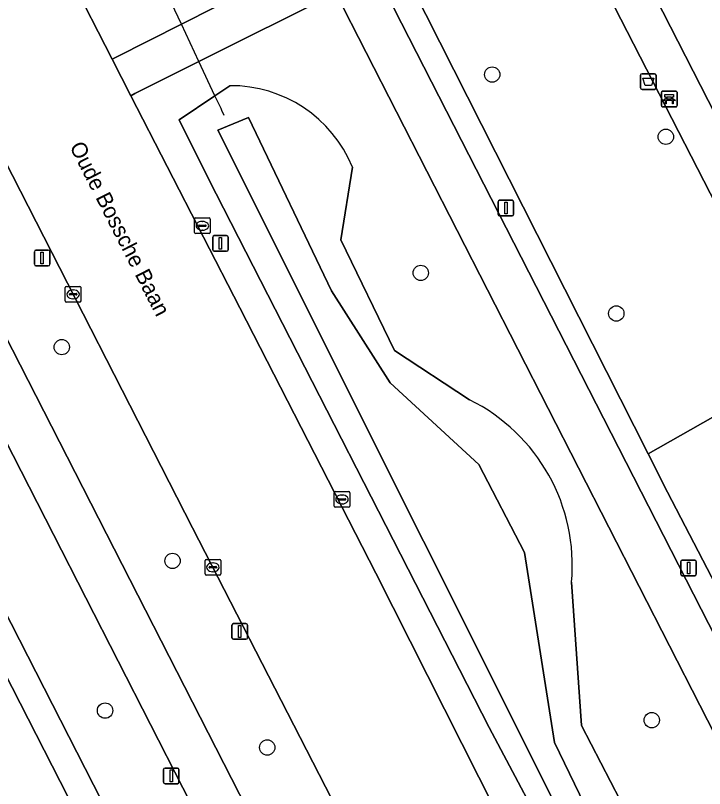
# Model space of a CAD drawing. Extents: x 159352 to 160617, y 385888 to 387323.
# Drawn here: x 159737.07 to 159781, y 386580.69 to 386630 of the extents above; entities that cross this region are included whole.
import ezdxf

# ---------------------------------------------------------------- set-up
doc = ezdxf.new("R2010")
doc.units = 0
for name, color, linetype in [('IMGEO_Afvalbak', 7, 'Continuous'), ('IMGEO_Bank', 7, 'Continuous'), ('IMGEO_Berm_groen', 7, 'Continuous'), ('IMGEO_Boom', 7, 'Continuous'), ('IMGEO_Duiker', 7, 'Continuous'), ('IMGEO_Fietspad_gesloten', 7, 'Continuous'), ('IMGEO_Groenvoorziening', 7, 'Continuous'), ('IMGEO_Kolk', 7, 'Continuous'), ('IMGEO_Lichtmast', 7, 'Continuous'), ('IMGEO_Oever', 7, 'Continuous'), ('IMGEO_Openbare_ruimte_label', 7, 'Continuous'), ('IMGEO_Rijbaan_lokaal_gesloten', 7, 'Continuous'), ('IMGEO_Verkeersbordpaal', 7, 'Continuous'), ('IMGEO_Voetpad_halfverhard', 7, 'Continuous'), ('IMGEO_Voetpad_open', 7, 'Continuous'), ('IMGEO_Waterloop', 7, 'Continuous')]:
    doc.layers.add(name, color=color, linetype=linetype)

msp = doc.modelspace()

# ---------------------------------------------------------------- linework, layer by layer
at = {"layer": 'IMGEO_Afvalbak'}
for p, q in [((159776.915, 386625.381), (159776.915, 386626.181)), ((159776.915, 386626.181), (159776.915, 386625.381)), ((159777.015, 386626.281), (159777.805, 386626.281)), ((159777.805, 386626.281), (159777.015, 386626.281)), ((159777.905, 386626.181), (159777.905, 386625.381)), ((159777.905, 386625.381), (159777.905, 386626.181)), ((159777.805, 386625.281), (159777.015, 386625.281)), ((159777.015, 386625.281), (159777.805, 386625.281))]:
    msp.add_line(p, q, dxfattribs=at)
msp.add_lwpolyline([(159777.058, 386625.995), (159777.762, 386625.995), (159777.613, 386625.525), (159777.207, 386625.525), (159777.058, 386625.995)], dxfattribs=at)
for centre, start, end in [((159777.015, 386626.181), 90, 180), ((159777.015, 386626.181), 90, 180), ((159777.805, 386626.181), 0, 90), ((159777.805, 386626.181), 360, 90), ((159777.015, 386625.381), 180, 270), ((159777.015, 386625.381), 180, 270), ((159777.805, 386625.381), 270, 0), ((159777.805, 386625.381), 270, 0)]:
    msp.add_arc(centre, 0.1, start, end, dxfattribs=at)
at = {"layer": 'IMGEO_Bank'}
for p, q in [((159778.244, 386624.243), (159778.244, 386625.084)), ((159778.244, 386625.084), (159778.244, 386624.243)), ((159778.319, 386625.168), (159779.16, 386625.168)), ((159779.16, 386625.168), (159778.319, 386625.168)), ((159779.244, 386625.093), (159779.244, 386624.252)), ((159779.244, 386624.252), (159779.244, 386625.093)), ((159778.941, 386624.566), (159778.548, 386624.566)), ((159778.553, 386624.674), (159778.553, 386624.78)), ((159778.597, 386624.78), (159778.597, 386624.674)), ((159778.885, 386624.786), (159778.603, 386624.786)), ((159778.603, 386624.668), (159778.885, 386624.668)), ((159778.891, 386624.674), (159778.891, 386624.78)), ((159778.935, 386624.78), (159778.935, 386624.674)), ((159779.169, 386624.168), (159778.328, 386624.168)), ((159778.328, 386624.168), (159779.169, 386624.168))]:
    msp.add_line(p, q, dxfattribs=at)
for points in [[(159778.491, 386624.566), (159778.349, 386624.566), (159778.461, 386624.668), (159778.547, 386624.668)], [(159778.547, 386624.786), (159778.461, 386624.786), (159778.461, 386624.947), (159779.024, 386624.947), (159779.024, 386624.786), (159778.941, 386624.786)], [(159778.541, 386624.559), (159778.541, 386624.352), (159778.498, 386624.352), (159778.498, 386624.559)], [(159778.941, 386624.668), (159779.024, 386624.668), (159779.136, 386624.566), (159778.997, 386624.566)], [(159778.991, 386624.559), (159778.991, 386624.352), (159778.947, 386624.352), (159778.947, 386624.559)]]:
    msp.add_lwpolyline(points, dxfattribs=at)
for centre, radius, start, end in [((159778.322, 386625.09), 0.0779, 92.4484, 184.2845), ((159778.322, 386625.09), 0.0779, 92.4484, 184.2845), ((159779.166, 386625.09), 0.0779, 2.4484, 94.2845), ((159779.166, 386625.09), 0.0779, 2.4484, 94.2845), ((159778.491, 386624.559), 0.00671, 2.8957, 87.1043), ((159778.548, 386624.559), 0.00671, 92.8957, 177.1043), ((159778.546, 386624.779), 0.00671, 2.8957, 87.1043), ((159778.546, 386624.675), 0.00671, 272.8957, 357.1043), ((159778.603, 386624.779), 0.00671, 92.8957, 177.1043), ((159778.603, 386624.675), 0.00671, 182.8957, 267.1043), ((159778.885, 386624.779), 0.00671, 2.8957, 87.1043), ((159778.885, 386624.675), 0.00671, 272.8957, 357.1043), ((159778.942, 386624.779), 0.00671, 92.8957, 177.1043), ((159778.942, 386624.675), 0.00671, 182.8957, 267.1043), ((159778.94, 386624.559), 0.00671, 2.8957, 87.1043), ((159778.997, 386624.559), 0.00671, 92.8957, 177.1043), ((159778.322, 386624.246), 0.0779, 182.4484, 274.2845), ((159778.322, 386624.246), 0.0779, 182.4484, 274.2845), ((159779.166, 386624.246), 0.0779, 272.4484, 4.2845), ((159779.166, 386624.246), 0.0779, 272.4484, 4.2845)]:
    msp.add_arc(centre, radius, start, end, dxfattribs=at)
at = {"layer": 'IMGEO_Berm_groen'}
for points in [[(159672.985, 386771.072), (159673.306, 386770.324), (159675.396, 386765.976), (159673.079, 386764.76), (159673.972, 386762.988), (159680.607, 386750), (159680.941, 386749.346), (159691.569, 386728.727), (159695.538, 386720.97), (159702.544, 386706.95), (159713.2, 386686.195), (159726.157, 386660.692), (159735.251, 386642.791), (159743.239, 386627.211), (159743.502, 386627.346), (159747.647, 386629.447), (159756.288, 386633.826), (159699.609, 386744.934), (159693.118, 386741.84), (159693.16, 386741.671), (159703.621, 386721.304), (159711.807, 386715.609)], [(159772.521, 386593.855), (159773.159, 386584.718), (159780.543, 386570.427), (159778.249, 386569.078), (159776.147, 386567.841), (159767.261, 386584.583), (159749.402, 386619.536), (159747.519, 386623.348), (159749.791, 386624.879), (159750.739, 386625.518)], [(159758.553, 386620.328), (159757.812, 386615.682), (159761.24, 386608.621), (159766.017, 386605.488)]]:
    msp.add_lwpolyline(points, dxfattribs=at)
for points in [[(159757.502, 386631.446), (159748.768, 386627.059), (159744.692, 386625.012), (159744.434, 386624.88), (159751.377, 386611.341), (159760.048, 386594.429), (159767.715, 386579.24), (159775.346, 386564.177), (159775.69, 386564.351), (159779.629, 386566.369), (159788.426, 386570.875)], [(159748.365, 386597.323), (159736.391, 386620.747), (159731.872, 386618.458), (159762.831, 386557.859), (159767.368, 386560.207), (159764.513, 386565.852)], [(159729.174, 386617.087), (159724.727, 386614.834), (159755.671, 386554.225), (159760.103, 386556.503)]]:
    msp.add_lwpolyline(points, close=True, dxfattribs=at)
for centre, radius, start, end in [((159750.804, 386617.138), 8.38, 22.3723, 90.4441), ((159760.765, 386594.917), 11.804, 354.8391, 63.58)]:
    msp.add_arc(centre, radius, start, end, dxfattribs=at)
at = {"layer": 'IMGEO_Boom'}
for centre in [(159767.462, 386626.226), (159778.529, 386622.256), (159762.909, 386613.579), (159775.373, 386610.988), (159740.026, 386608.843), (159747.085, 386595.211), (159742.784, 386585.664), (159777.632, 386585.055), (159753.122, 386583.311)]:
    msp.add_circle(centre, 0.489, dxfattribs=at)
at = {"layer": 'IMGEO_Duiker'}
msp.add_lwpolyline([(159750.382, 386623.621), (159750.234, 386623.935), (159750.18, 386624.052), (159749.791, 386624.879), (159748.768, 386627.059), (159747.647, 386629.447), (159746.597, 386631.685), (159746.295, 386632.327), (159746.229, 386632.469), (159746.117, 386632.707)], dxfattribs=at)
at = {"layer": 'IMGEO_Fietspad_gesloten'}
for points in [[(159676.451, 386789.766), (159676.823, 386789.968), (159680.292, 386783.231), (159681.255, 386781.361), (159681.072, 386781.273), (159687.819, 386768.047), (159699.609, 386744.934), (159756.288, 386633.826), (159757.502, 386631.446), (159788.426, 386570.875), (159789.556, 386568.692), (159791.68, 386564.586)], [(159848.46, 386459.683), (159802.183, 386550.232), (159802.147, 386550.232), (159796.524, 386561.299), (159796.533, 386561.328), (159758.813, 386635.137), (159682.71, 386784.054)], [(159764.732, 386554.032), (159763.906, 386555.697), (159762.831, 386557.859), (159731.872, 386618.458), (159729.174, 386617.087), (159760.103, 386556.503), (159761.201, 386554.351), (159763.897, 386548.665), (159768.25, 386540.122)]]:
    msp.add_lwpolyline(points, dxfattribs=at)
at = {"layer": 'IMGEO_Groenvoorziening'}
for points in [[(159825.984, 386620.301), (159803.216, 386654.811), (159777.559, 386641.849), (159773.515, 386639.685), (159811.594, 386565.163), (159844.748, 386581.785), (159829.347, 386614.249)], [(159753.143, 386555.26), (159723.124, 386614.022), (159719.418, 386611.743), (159714.799, 386608.404), (159706.083, 386601.493), (159745.173, 386546.684), (159752.276, 386551.753)]]:
    msp.add_lwpolyline(points, dxfattribs=at)
for points in [[(159777.398, 386602.033), (159787.079, 386607.514), (159771.173, 386638.525), (159767.969, 386636.897), (159761.46, 386633.56)], [(159778.634, 386599.588), (159797.7, 386562.907), (159805.918, 386562.302), (159809.376, 386564.045), (159787.079, 386607.514), (159777.398, 386602.033)]]:
    msp.add_lwpolyline(points, close=True, dxfattribs=at)
at = {"layer": 'IMGEO_Kolk'}
for p, q in [((159748.563, 386617.082), (159749.415, 386617.082)), ((159748.488, 386616.156), (159748.488, 386617.008)), ((159748.747, 386616.576), (159748.747, 386616.588)), ((159748.79, 386616.625), (159749.188, 386616.625)), ((159748.976, 386616.862), (159749.001, 386616.862)), ((159749.231, 386616.588), (159749.231, 386616.576)), ((159749.489, 386617.008), (159749.489, 386616.156)), ((159749.415, 386616.082), (159748.563, 386616.082)), ((159749.185, 386616.539), (159748.787, 386616.539)), ((159748.999, 386616.302), (159748.974, 386616.302)), ((159740.25, 386611.788), (159740.25, 386612.64)), ((159740.325, 386612.714), (159741.177, 386612.714)), ((159741.251, 386612.64), (159741.251, 386611.788)), ((159740.509, 386612.208), (159740.509, 386612.22)), ((159740.947, 386612.171), (159740.549, 386612.171)), ((159740.552, 386612.257), (159740.95, 386612.257)), ((159740.738, 386612.494), (159740.763, 386612.494)), ((159740.993, 386612.22), (159740.993, 386612.208)), ((159741.177, 386611.714), (159740.325, 386611.714)), ((159740.761, 386611.934), (159740.736, 386611.934)), ((159757.385, 386598.705), (159757.385, 386599.557)), ((159757.46, 386599.631), (159758.312, 386599.631)), ((159757.873, 386599.411), (159757.898, 386599.411)), ((159758.386, 386599.557), (159758.386, 386598.705)), ((159757.644, 386599.125), (159757.644, 386599.137)), ((159758.082, 386599.088), (159757.684, 386599.088)), ((159757.687, 386599.174), (159758.085, 386599.174)), ((159757.896, 386598.851), (159757.871, 386598.851)), ((159758.128, 386599.137), (159758.128, 386599.125)), ((159758.312, 386598.631), (159757.46, 386598.631)), ((159749.156, 386594.376), (159749.156, 386595.228)), ((159749.231, 386595.302), (159750.083, 386595.302)), ((159749.644, 386595.082), (159749.669, 386595.082)), ((159750.157, 386595.228), (159750.157, 386594.376)), ((159749.415, 386594.796), (159749.415, 386594.808)), ((159749.853, 386594.759), (159749.455, 386594.759)), ((159749.458, 386594.845), (159749.856, 386594.845)), ((159749.667, 386594.522), (159749.642, 386594.522)), ((159749.899, 386594.808), (159749.899, 386594.796)), ((159750.083, 386594.302), (159749.231, 386594.302))]:
    msp.add_line(p, q, dxfattribs=at)
for points in [[(159748.563, 386617.082), (159749.415, 386617.082)], [(159748.488, 386616.156), (159748.488, 386617.008)], [(159749.489, 386617.008), (159749.489, 386616.156)], [(159749.415, 386616.082), (159748.563, 386616.082)], [(159740.25, 386611.788), (159740.25, 386612.64)], [(159740.325, 386612.714), (159741.177, 386612.714)], [(159741.251, 386612.64), (159741.251, 386611.788)], [(159741.177, 386611.714), (159740.325, 386611.714)], [(159757.385, 386598.705), (159757.385, 386599.557)], [(159757.46, 386599.631), (159758.312, 386599.631)], [(159758.386, 386599.557), (159758.386, 386598.705)], [(159758.312, 386598.631), (159757.46, 386598.631)], [(159749.156, 386594.376), (159749.156, 386595.228)], [(159749.231, 386595.302), (159750.083, 386595.302)], [(159750.157, 386595.228), (159750.157, 386594.376)], [(159750.083, 386594.302), (159749.231, 386594.302)]]:
    msp.add_lwpolyline(points, dxfattribs=at)
for centre, radius, start, end in [((159748.565, 386617.006), 0.0765, 91.552, 178.448), ((159748.565, 386617.006), 0.0765, 91.552, 178.448), ((159749.413, 386617.006), 0.0765, 1.552, 88.448), ((159749.413, 386617.006), 0.0765, 1.552, 88.448), ((159748.787, 386616.585), 0.0403, 85.8775, 175.7526), ((159748.784, 386616.575), 0.0366, 178.938, 274.7102), ((159749.188, 386616.582), 0.043, 264.8664, 352.4533), ((159749.192, 386616.587), 0.0386, 1.7309, 96.639), ((159748.565, 386616.158), 0.0765, 181.552, 268.448), ((159748.565, 386616.158), 0.0765, 181.552, 268.448), ((159749.413, 386616.158), 0.0765, 271.552, 358.448), ((159749.413, 386616.158), 0.0765, 271.552, 358.448), ((159740.327, 386612.638), 0.0765, 91.552, 178.448), ((159740.327, 386612.638), 0.0765, 91.552, 178.448), ((159741.175, 386612.638), 0.0765, 1.552, 88.448), ((159741.175, 386612.638), 0.0765, 1.552, 88.448), ((159740.549, 386612.217), 0.0403, 85.8775, 175.7526), ((159740.546, 386612.207), 0.0366, 178.938, 274.7102), ((159740.95, 386612.214), 0.043, 264.8664, 352.4533), ((159740.954, 386612.219), 0.0386, 1.7309, 96.639), ((159740.327, 386611.79), 0.0765, 181.552, 268.448), ((159740.327, 386611.79), 0.0765, 181.552, 268.448), ((159741.175, 386611.79), 0.0765, 271.552, 358.448), ((159741.175, 386611.79), 0.0765, 271.552, 358.448), ((159757.462, 386599.555), 0.0765, 91.552, 178.448), ((159757.462, 386599.555), 0.0765, 91.552, 178.448), ((159758.31, 386599.555), 0.0765, 1.552, 88.448), ((159758.31, 386599.555), 0.0765, 1.552, 88.448), ((159757.684, 386599.134), 0.0403, 85.8775, 175.7526), ((159757.681, 386599.124), 0.0366, 178.938, 274.7102), ((159758.085, 386599.131), 0.043, 264.8664, 352.4533), ((159758.089, 386599.136), 0.0386, 1.7309, 96.639), ((159757.462, 386598.707), 0.0765, 181.552, 268.448), ((159757.462, 386598.707), 0.0765, 181.552, 268.448), ((159758.31, 386598.707), 0.0765, 271.552, 358.448), ((159758.31, 386598.707), 0.0765, 271.552, 358.448), ((159749.233, 386595.226), 0.0765, 91.552, 178.448), ((159749.233, 386595.226), 0.0765, 91.552, 178.448), ((159750.081, 386595.226), 0.0765, 1.552, 88.448), ((159750.081, 386595.226), 0.0765, 1.552, 88.448), ((159749.455, 386594.805), 0.0403, 85.8775, 175.7526), ((159749.452, 386594.795), 0.0366, 178.938, 274.7102), ((159749.856, 386594.802), 0.043, 264.8664, 352.4533), ((159749.86, 386594.807), 0.0386, 1.7309, 96.639), ((159749.233, 386594.378), 0.0765, 181.552, 268.448), ((159749.233, 386594.378), 0.0765, 181.552, 268.448), ((159750.081, 386594.378), 0.0765, 271.552, 358.448), ((159750.081, 386594.378), 0.0765, 271.552, 358.448)]:
    msp.add_arc(centre, radius, start, end, dxfattribs=at)
for centre, major_axis, ratio, start_param, end_param in [((159748.975, 386616.582), (-0.387, 0.002), 0.722429, 4.712389, 7.853982), ((159749, 386616.582), (-0.39, 0.002), 0.717154, 1.570796, 4.712389), ((159740.737, 386612.214), (-0.387, 0.002), 0.722429, 4.712389, 7.853982), ((159740.762, 386612.214), (-0.39, 0.002), 0.717154, 1.570796, 4.712389), ((159757.872, 386599.131), (-0.387, 0.002), 0.722429, 4.712389, 7.853982), ((159757.897, 386599.131), (-0.39, 0.002), 0.717154, 1.570796, 4.712389), ((159749.643, 386594.802), (-0.387, 0.002), 0.722429, 4.712389, 7.853982), ((159749.668, 386594.802), (-0.39, 0.002), 0.717154, 1.570796, 4.712389)]:
    msp.add_ellipse(centre, major_axis=major_axis, ratio=ratio, start_param=start_param, end_param=end_param, dxfattribs=at)
at = {"layer": 'IMGEO_Lichtmast'}
for p, q in [((159767.837, 386617.309), (159767.837, 386618.109)), ((159767.837, 386618.109), (159767.837, 386617.309)), ((159767.937, 386618.209), (159768.727, 386618.209)), ((159768.727, 386618.209), (159767.937, 386618.209)), ((159768.827, 386618.109), (159768.827, 386617.309)), ((159768.827, 386617.309), (159768.827, 386618.109)), ((159768.727, 386617.209), (159767.937, 386617.209)), ((159767.937, 386617.209), (159768.727, 386617.209)), ((159749.645, 386615.058), (159749.645, 386615.858)), ((159749.645, 386615.858), (159749.645, 386615.058)), ((159749.745, 386615.958), (159750.535, 386615.958)), ((159750.535, 386615.958), (159749.745, 386615.958)), ((159750.635, 386615.858), (159750.635, 386615.058)), ((159750.635, 386615.058), (159750.635, 386615.858)), ((159750.535, 386614.958), (159749.745, 386614.958)), ((159749.745, 386614.958), (159750.535, 386614.958)), ((159779.48, 386594.363), (159779.48, 386595.163)), ((159779.48, 386595.163), (159779.48, 386594.363)), ((159779.58, 386595.263), (159780.37, 386595.263)), ((159780.37, 386595.263), (159779.58, 386595.263)), ((159780.47, 386595.163), (159780.47, 386594.363)), ((159780.47, 386594.363), (159780.47, 386595.163)), ((159780.37, 386594.263), (159779.58, 386594.263)), ((159779.58, 386594.263), (159780.37, 386594.263)), ((159750.874, 386590.31), (159750.874, 386591.11)), ((159750.874, 386591.11), (159750.874, 386590.31)), ((159750.974, 386591.21), (159751.764, 386591.21)), ((159751.764, 386591.21), (159750.974, 386591.21)), ((159751.864, 386591.11), (159751.864, 386590.31)), ((159751.864, 386590.31), (159751.864, 386591.11)), ((159751.764, 386590.21), (159750.974, 386590.21)), ((159750.974, 386590.21), (159751.764, 386590.21)), ((159746.507, 386581.102), (159746.507, 386581.902)), ((159746.507, 386581.902), (159746.507, 386581.102)), ((159746.607, 386582.002), (159747.397, 386582.002)), ((159747.397, 386582.002), (159746.607, 386582.002)), ((159747.497, 386581.902), (159747.497, 386581.102)), ((159747.497, 386581.102), (159747.497, 386581.902)), ((159747.397, 386581.002), (159746.607, 386581.002)), ((159746.607, 386581.002), (159747.397, 386581.002))]:
    msp.add_line(p, q, dxfattribs=at)
for points in [[(159768.257, 386618.084), (159768.407, 386618.084), (159768.407, 386617.334), (159768.257, 386617.334), (159768.257, 386618.084)], [(159750.065, 386615.833), (159750.215, 386615.833), (159750.215, 386615.083), (159750.065, 386615.083), (159750.065, 386615.833)], [(159779.9, 386595.138), (159780.05, 386595.138), (159780.05, 386594.388), (159779.9, 386594.388), (159779.9, 386595.138)], [(159751.294, 386591.085), (159751.444, 386591.085), (159751.444, 386590.335), (159751.294, 386590.335), (159751.294, 386591.085)], [(159746.927, 386581.877), (159747.077, 386581.877), (159747.077, 386581.127), (159746.927, 386581.127), (159746.927, 386581.877)]]:
    msp.add_lwpolyline(points, dxfattribs=at)
for centre, start, end in [((159767.937, 386618.109), 90, 180), ((159767.937, 386618.109), 90, 180), ((159768.727, 386618.109), 0, 90), ((159768.727, 386618.109), 360, 90), ((159767.937, 386617.309), 180, 270), ((159767.937, 386617.309), 180, 270), ((159768.727, 386617.309), 270, 0), ((159768.727, 386617.309), 270, 0), ((159749.745, 386615.858), 90, 180), ((159749.745, 386615.858), 90, 180), ((159750.535, 386615.858), 0, 90), ((159750.535, 386615.858), 360, 90), ((159749.745, 386615.058), 180, 270), ((159749.745, 386615.058), 180, 270), ((159750.535, 386615.058), 270, 0), ((159750.535, 386615.058), 270, 0), ((159779.58, 386595.163), 90, 180), ((159779.58, 386595.163), 90, 180), ((159780.37, 386595.163), 0, 90), ((159780.37, 386595.163), 360, 90), ((159779.58, 386594.363), 180, 270), ((159779.58, 386594.363), 180, 270), ((159780.37, 386594.363), 270, 0), ((159780.37, 386594.363), 270, 0), ((159750.974, 386591.11), 90, 180), ((159750.974, 386591.11), 90, 180), ((159751.764, 386591.11), 0, 90), ((159751.764, 386591.11), 360, 90), ((159750.974, 386590.31), 180, 270), ((159750.974, 386590.31), 180, 270), ((159751.764, 386590.31), 270, 0), ((159751.764, 386590.31), 270, 0), ((159746.607, 386581.902), 90, 180), ((159746.607, 386581.902), 90, 180), ((159747.397, 386581.902), 0, 90), ((159747.397, 386581.902), 360, 90), ((159746.607, 386581.102), 180, 270), ((159746.607, 386581.102), 180, 270), ((159747.397, 386581.102), 270, 0), ((159747.397, 386581.102), 270, 0)]:
    msp.add_arc(centre, 0.1, start, end, dxfattribs=at)
at = {"layer": 'IMGEO_Oever'}
for points in [[(159750.739, 386625.518), (159749.791, 386624.879), (159747.519, 386623.348), (159749.402, 386619.536), (159767.261, 386584.583), (159776.147, 386567.841), (159778.249, 386569.078), (159780.543, 386570.427), (159773.159, 386584.718), (159772.521, 386593.855)], [(159766.017, 386605.488), (159761.24, 386608.621), (159757.812, 386615.682), (159758.553, 386620.328)]]:
    msp.add_lwpolyline(points, dxfattribs=at)
msp.add_lwpolyline([(159749.978, 386622.688), (159751.936, 386623.497), (159757.212, 386612.433), (159760.957, 386606.561), (159766.616, 386601.369), (159769.51, 386595.752), (159771.425, 386583.624), (159777.51, 386571.071), (159776.191, 386570.263)], close=True, dxfattribs=at)
for centre, radius, start, end in [((159750.804, 386617.138), 8.38, 22.3723, 90.4441), ((159760.765, 386594.917), 11.804, 354.8391, 63.58)]:
    msp.add_arc(centre, radius, start, end, dxfattribs=at)
at = {"layer": 'IMGEO_Rijbaan_lokaal_gesloten'}
for points in [[(159760.048, 386594.429), (159751.377, 386611.341), (159744.434, 386624.88), (159743.239, 386627.211), (159735.251, 386642.791), (159726.157, 386660.692), (159713.2, 386686.195), (159702.544, 386706.95), (159695.538, 386720.97), (159691.569, 386728.727), (159680.941, 386749.346), (159680.607, 386750), (159673.972, 386762.988), (159673.079, 386764.76), (159670.445, 386763.296), (159670.633, 386762.927), (159670.915, 386762.369)], [(159726.632, 386639.935), (159735.19, 386623.096), (159736.391, 386620.747), (159748.365, 386597.323), (159764.513, 386565.852), (159767.368, 386560.207), (159768.484, 386557.998), (159769.496, 386555.998), (159770.939, 386553.145), (159775.227, 386544.663), (159788.695, 386518.297), (159798.065, 386500), (159800.637, 386494.977), (159813.085, 386470.573), (159815.835, 386465.634), (159820.176, 386457.104), (159822.851, 386458.49), (159822.66, 386458.865), (159822.317, 386459.512)], [(159824.135, 386460.402), (159824.463, 386459.766), (159824.675, 386459.355), (159828.146, 386461.016), (159818.737, 386479.588), (159803.611, 386509.06), (159794.04, 386527.707), (159778.839, 386557.281), (159777.448, 386560.027), (159776.891, 386561.126), (159776.439, 386562.02), (159775.346, 386564.177), (159767.715, 386579.24), (159760.048, 386594.429)]]:
    msp.add_lwpolyline(points, dxfattribs=at)
at = {"layer": 'IMGEO_Verkeersbordpaal'}
for p, q in [((159738.278, 386614.125), (159738.278, 386614.925)), ((159738.278, 386614.925), (159738.278, 386614.125)), ((159738.378, 386615.025), (159739.168, 386615.025)), ((159739.168, 386615.025), (159738.378, 386615.025)), ((159739.268, 386614.925), (159739.268, 386614.125)), ((159739.268, 386614.125), (159739.268, 386614.925)), ((159739.168, 386614.025), (159738.378, 386614.025)), ((159738.378, 386614.025), (159739.168, 386614.025))]:
    msp.add_line(p, q, dxfattribs=at)
msp.add_lwpolyline([(159738.698, 386614.9), (159738.848, 386614.9), (159738.848, 386614.15), (159738.698, 386614.15), (159738.698, 386614.9)], dxfattribs=at)
for centre, start, end in [((159738.378, 386614.925), 90, 180), ((159738.378, 386614.925), 90, 180), ((159739.168, 386614.925), 0, 90), ((159739.168, 386614.925), 360, 90), ((159738.378, 386614.125), 180, 270), ((159738.378, 386614.125), 180, 270), ((159739.168, 386614.125), 270, 0), ((159739.168, 386614.125), 270, 0)]:
    msp.add_arc(centre, 0.1, start, end, dxfattribs=at)
at = {"layer": 'IMGEO_Voetpad_halfverhard'}
for points in [[(159773.515, 386639.685), (159771.173, 386638.525), (159787.079, 386607.514), (159809.376, 386564.045), (159811.594, 386565.163)], [(159757.502, 386631.446), (159756.288, 386633.826), (159747.647, 386629.447), (159743.502, 386627.346), (159743.239, 386627.211), (159744.434, 386624.88), (159744.692, 386625.012), (159748.768, 386627.059)]]:
    msp.add_lwpolyline(points, close=True, dxfattribs=at)
at = {"layer": 'IMGEO_Voetpad_open'}
for points in [[(159682.71, 386784.054), (159758.813, 386635.137), (159796.533, 386561.328)], [(159798.962, 386559.727), (159799.359, 386559.682), (159797.7, 386562.907), (159778.634, 386599.588), (159777.398, 386602.033), (159761.46, 386633.56)]]:
    msp.add_lwpolyline(points, dxfattribs=at)
msp.add_lwpolyline([(159761.201, 386554.351), (159760.103, 386556.503), (159755.671, 386554.225), (159724.727, 386614.834), (159723.124, 386614.022), (159753.143, 386555.26), (159753.146, 386555.261), (159756.902, 386547.807), (159761.403, 386538.922), (159762.483, 386540.891), (159756.788, 386552.065)], close=True, dxfattribs=at)
at = {"layer": 'IMGEO_Waterloop'}
msp.add_lwpolyline([(159749.978, 386622.688), (159776.191, 386570.263), (159777.51, 386571.071), (159771.425, 386583.624), (159769.51, 386595.752), (159766.616, 386601.369), (159760.957, 386606.561), (159757.212, 386612.433), (159751.936, 386623.497)], close=True, dxfattribs=at)

# ---------------------------------------------------------------- texts
at = {"layer": 'IMGEO_Openbare_ruimte_label'}
msp.add_text('Oude Bossche Baan', height=1, rotation=297.0778, dxfattribs=at).set_placement((159740.498, 386621.636))

doc.saveas('drawing.dxf')
